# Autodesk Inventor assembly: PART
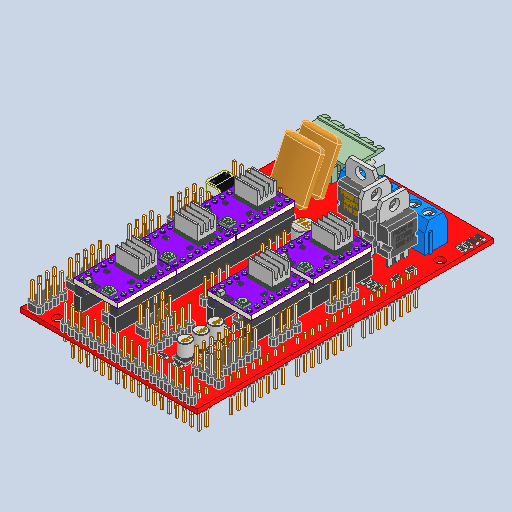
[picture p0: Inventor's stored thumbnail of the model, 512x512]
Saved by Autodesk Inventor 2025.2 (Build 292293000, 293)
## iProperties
Created: 2025-04
Part Number: PART
Description: PART--DESC
Document SubType Name: Assembly
Designer: BennF
Author: BennF
Revision Number: NONE
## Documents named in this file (15)
- C:\Users\BennF\Nextcloud\Benutzer\CNC JarBeRi\existing parts\Electronics\RepRap A4988 Shied (USE WITHOUT ARDUINO)\reprap-a4988-1.snapshot.1\RepRap\RepRap\PART.iam
- C:\Users\BennF\Nextcloud\Benutzer\CNC JarBeRi\existing parts\Electronics\RepRap A4988 Shied (USE WITHOUT ARDUINO)\reprap-a4988-1.snapshot.1\RepRap\RepRap\PART Geometry.ipt
- C:\Users\BennF\Nextcloud\Benutzer\CNC JarBeRi\existing parts\Electronics\RepRap A4988 Shied (USE WITHOUT ARDUINO)\reprap-a4988-1.snapshot.1\RepRap\RepRap\Terminal.iam
- C:\Users\BennF\Nextcloud\Benutzer\CNC JarBeRi\existing parts\Electronics\RepRap A4988 Shied (USE WITHOUT ARDUINO)\reprap-a4988-1.snapshot.1\RepRap\RepRap\P60NF.iam
- C:\Users\BennF\Nextcloud\Benutzer\CNC JarBeRi\existing parts\Electronics\RepRap A4988 Shied (USE WITHOUT ARDUINO)\reprap-a4988-1.snapshot.1\RepRap\RepRap\P55NF.iam
- C:\Users\BennF\Nextcloud\Benutzer\CNC JarBeRi\existing parts\Electronics\RepRap A4988 Shied (USE WITHOUT ARDUINO)\reprap-a4988-1.snapshot.1\RepRap\RepRap\P60NF_1.iam
- C:\Users\BennF\Nextcloud\Benutzer\CNC JarBeRi\existing parts\Electronics\RepRap A4988 Shied (USE WITHOUT ARDUINO)\reprap-a4988-1.snapshot.1\RepRap\RepRap\N.iam
- C:\Users\BennF\Nextcloud\Benutzer\CNC JarBeRi\existing parts\Electronics\RepRap A4988 Shied (USE WITHOUT ARDUINO)\reprap-a4988-1.snapshot.1\RepRap\RepRap\Pins2.iam
- C:\Users\BennF\Nextcloud\Benutzer\CNC JarBeRi\existing parts\Electronics\RepRap A4988 Shied (USE WITHOUT ARDUINO)\reprap-a4988-1.snapshot.1\RepRap\RepRap\c.iam
- C:\Users\BennF\Nextcloud\Benutzer\CNC JarBeRi\existing parts\Electronics\RepRap A4988 Shied (USE WITHOUT ARDUINO)\reprap-a4988-1.snapshot.1\RepRap\RepRap\PBsw-Ver.iam
- C:\Users\BennF\Nextcloud\Benutzer\CNC JarBeRi\existing parts\Electronics\RepRap A4988 Shied (USE WITHOUT ARDUINO)\reprap-a4988-1.snapshot.1\RepRap\RepRap\ARDUINO-pins.iam
- C:\Users\BennF\Nextcloud\Benutzer\CNC JarBeRi\existing parts\Electronics\RepRap A4988 Shied (USE WITHOUT ARDUINO)\reprap-a4988-1.snapshot.1\RepRap\RepRap\R.iam
- C:\Users\BennF\Nextcloud\Benutzer\CNC JarBeRi\existing parts\Electronics\RepRap A4988 Shied (USE WITHOUT ARDUINO)\reprap-a4988-1.snapshot.1\RepRap\RepRap\LED.iam
- C:\Users\BennF\Nextcloud\Benutzer\CNC JarBeRi\existing parts\Electronics\RepRap A4988 Shied (USE WITHOUT ARDUINO)\reprap-a4988-1.snapshot.1\RepRap\RepRap\U.iam
- C:\Users\BennF\Nextcloud\Benutzer\CNC JarBeRi\existing parts\Electronics\RepRap A4988 Shied (USE WITHOUT ARDUINO)\reprap-a4988-1.snapshot.1\RepRap\RepRap\Diod.iam
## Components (14 placed, 13 different names)
1. PART Geometry
2. Terminal [sub-assembly]
3. P60NF [sub-assembly]
4. P55NF [sub-assembly]
5. P60NF:1 [sub-assembly]
6. N [sub-assembly]
7. Pins2 [sub-assembly]
8. c [sub-assembly]
9. PBsw-Ver [sub-assembly]
10. ARDUINO-pins [sub-assembly]
11. R [sub-assembly]
12. LED [sub-assembly]
13. U [sub-assembly]
14. Diod [sub-assembly]
